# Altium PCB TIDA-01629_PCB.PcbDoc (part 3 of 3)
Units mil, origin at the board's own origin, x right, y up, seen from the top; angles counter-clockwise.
Board outline 2351.88 x 2559.06 mil, 4 copper layers (Top Layer, GND, POWER, Bottom Layer), stack 60.63 mil thick; 223 components, 122 nets, 655 pads, 542 vias.
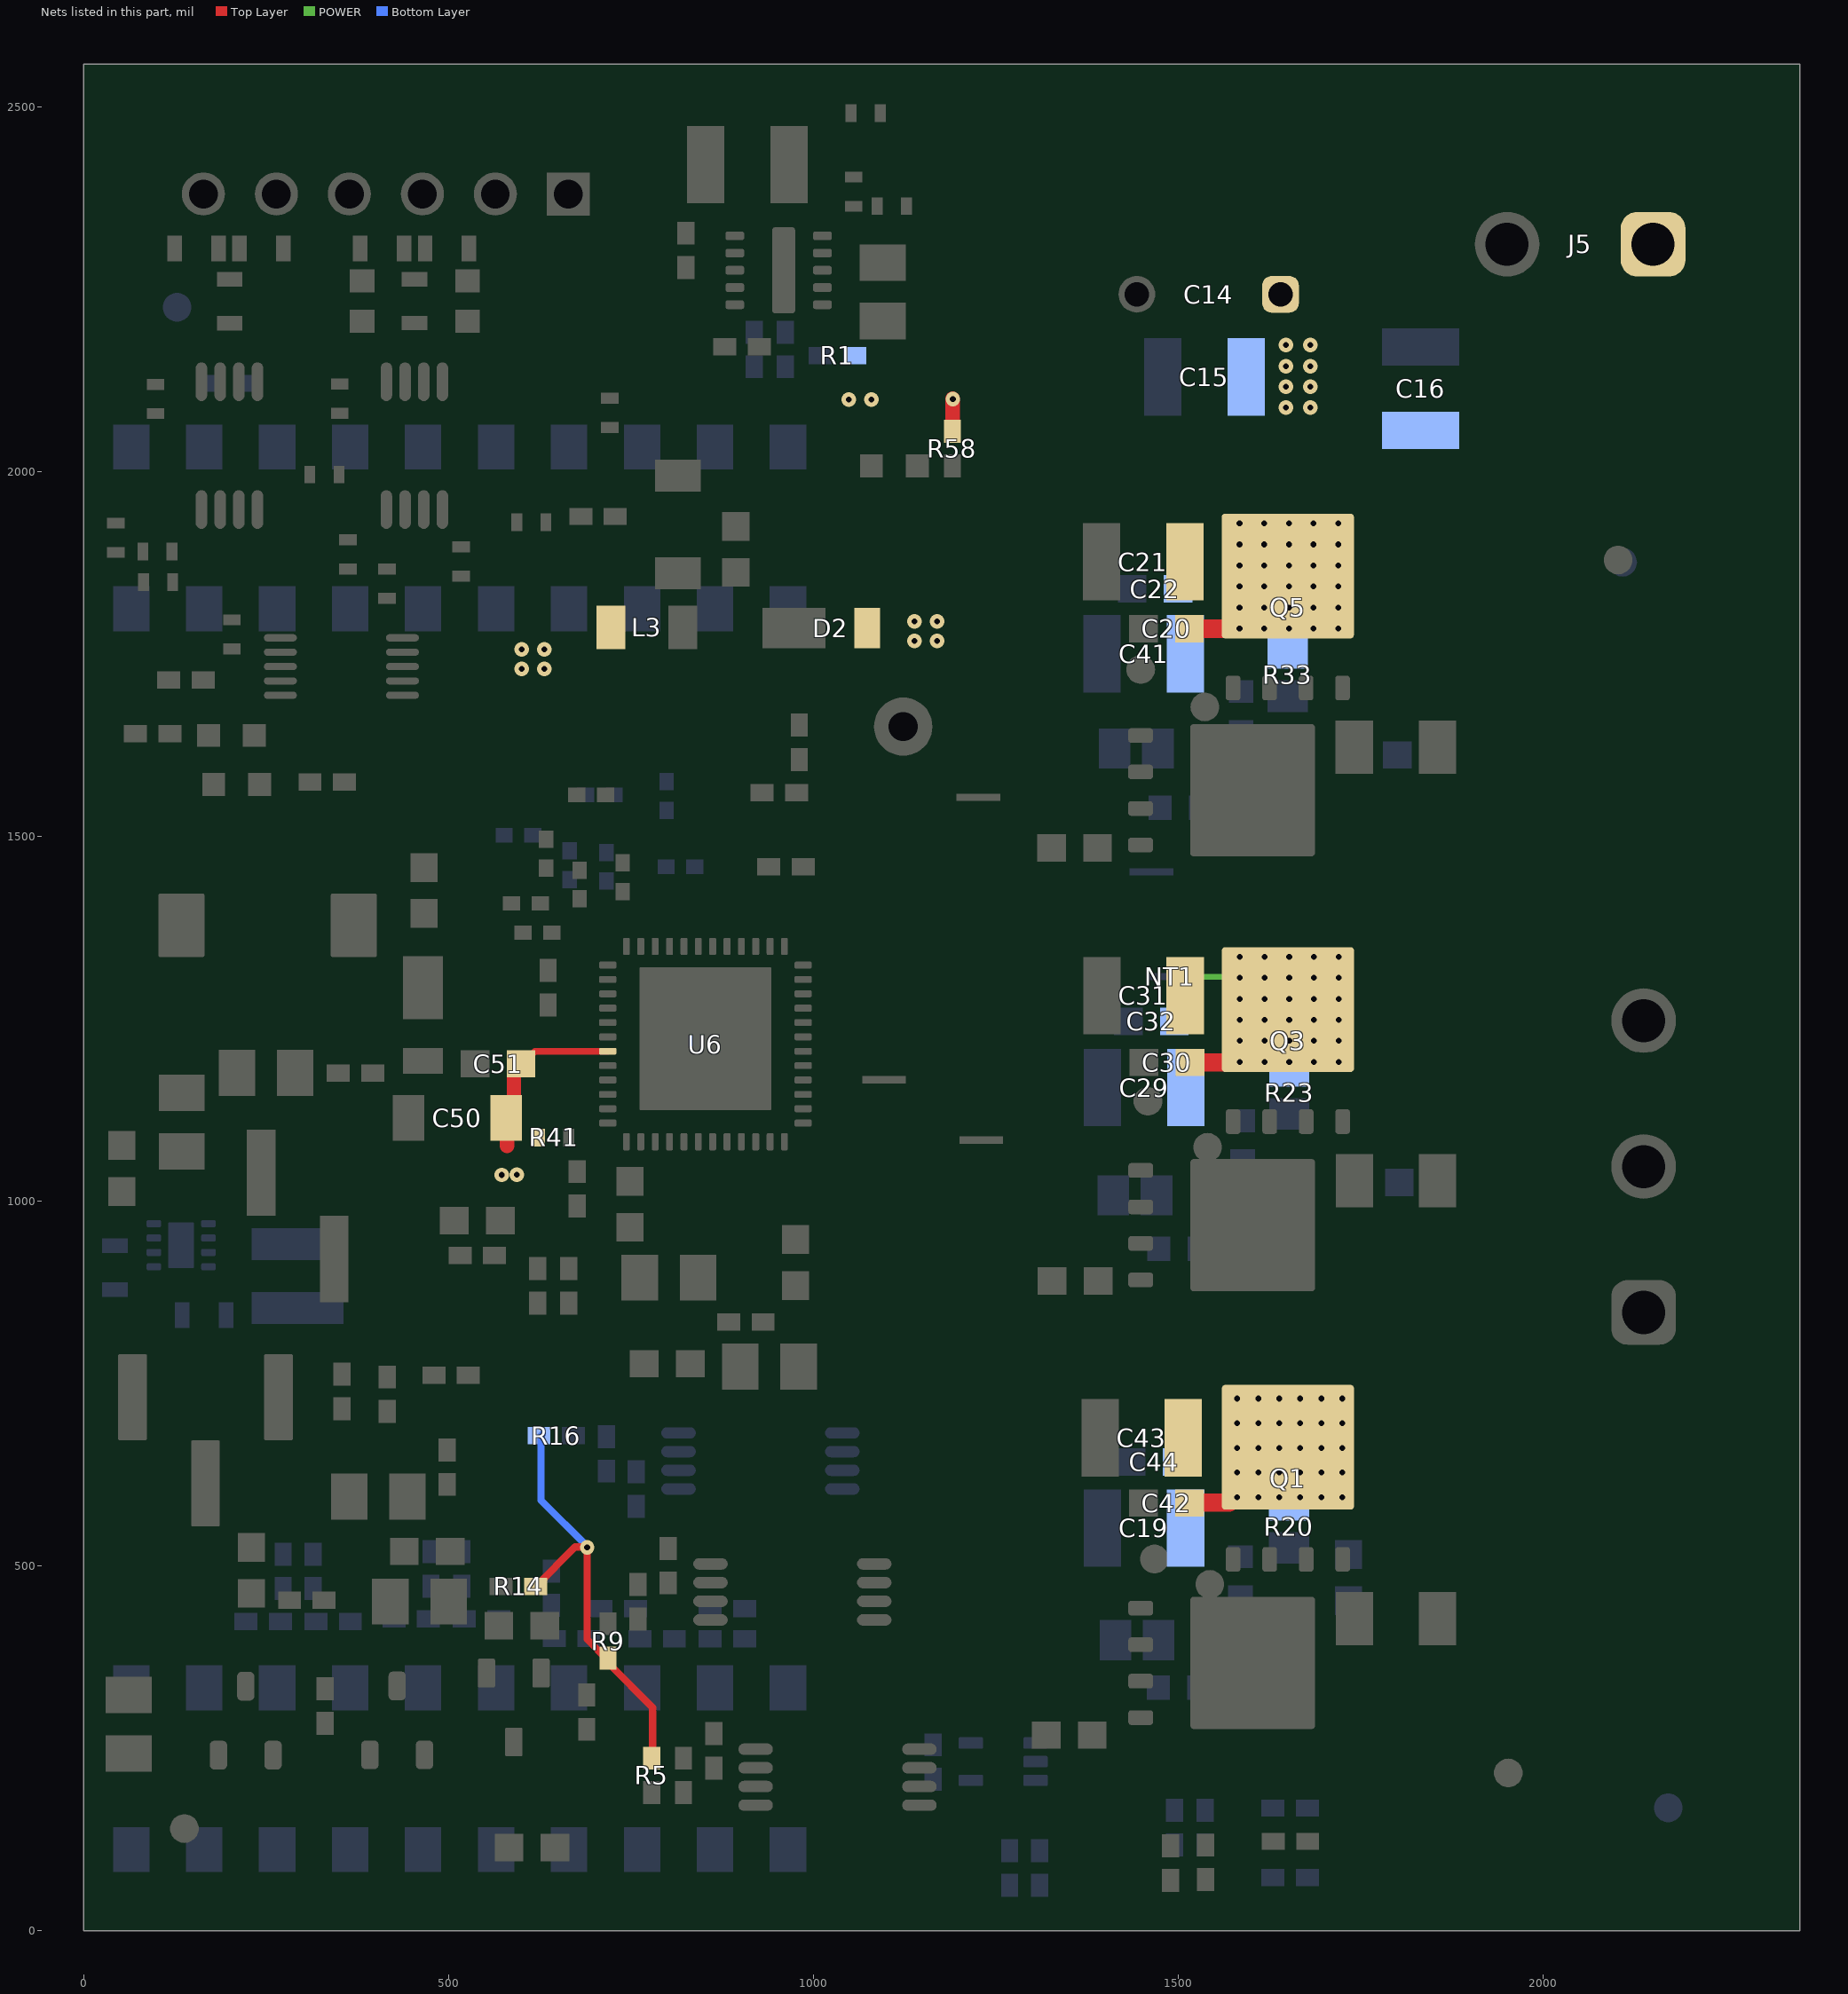
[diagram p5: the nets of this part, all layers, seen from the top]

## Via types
v1: diameter 20, hole 8, Top Layer to Bottom Layer, tented both sides, 525 vias
v2: diameter 19.68, hole 7.87, Top Layer to Bottom Layer, 17 vias

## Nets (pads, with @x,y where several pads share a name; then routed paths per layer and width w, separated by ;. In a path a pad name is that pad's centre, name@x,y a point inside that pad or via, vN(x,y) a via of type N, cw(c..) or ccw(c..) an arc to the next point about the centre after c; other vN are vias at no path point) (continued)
Vin: C14.1 C15.1 C16.1 C19.1 C20.1 C21.1 C22.1 C29.1 C30.1 C31.1 C32.1 C41.1 C42.1 C43.1 C44.1 D2.2 J5.1 NT1.2 Q1.5 Q1.6 Q1.7 Q1.8 Q1.9@1650.49,662.94 Q3.5 Q3.6 Q3.7 Q3.8 Q3.9@1650.49,1262.92 Q5.5 Q5.6 Q5.7 Q5.8 Q5.9@1650.36,1857.21 R1.1 R20.2 R23.2 R33.2 R58.2 | length 286.2
  Top Layer w20: R58.2@1191.05,2053.88 v1@1191.05,2100.27
  Top Layer w25: C20.1@1515.52,1784.92 Q5.9@1568.99,1784.92 ; C42.1@1515.68,586.51 1515.96,586.51 1516.52,587.07 Q1.9@1569.85,587.07 ; C30.1@1516.29,1190.55 Q3.9@1569.97,1190.55
  POWER w8: 1504.37,1307.87 v1@1582.68,1307.87
  other v1: 1581.04,594.57 1609.85,594.57 1638.66,594.57 1667.46,594.57 1696.27,594.57 1725.07,594.57 1581.04,628.37 1609.85,628.37 1638.66,628.37 1667.46,628.37 1696.27,628.37 1725.07,628.37 1581.04,662.17 1609.85,662.17 1638.66,662.17 1667.46,662.17 1696.27,662.17 1725.07,662.17 1581.04,695.97 1609.85,695.97 1638.66,695.97 1667.46,695.97 1696.27,695.97 1725.07,695.97 1581.04,729.76 1609.85,729.76 1638.66,729.76 1667.46,729.76 1696.27,729.76 1725.07,729.76 1584.73,1191.2 1618.53,1191.2 1652.33,1191.2 1686.12,1191.2 1719.92,1191.2 1584.73,1220.01 1618.53,1220.01 1652.33,1220.01 1686.12,1220.01 1719.92,1220.01 1584.73,1248.81 1618.53,1248.81 1652.33,1248.81 1686.12,1248.81 1719.92,1248.81 1584.73,1277.62 1618.53,1277.62 1652.33,1277.62 1686.12,1277.62 1719.92,1277.62 1584.73,1306.42 1618.53,1306.42 1652.33,1306.42 1686.12,1306.42 1719.92,1306.42 1584.73,1335.23 1618.53,1335.23 1652.33,1335.23 1686.12,1335.23 1719.92,1335.23 1138.63,1768.24 1169.56,1768.24 1584.24,1785.19 1618.04,1785.19 1651.84,1785.19 1685.64,1785.19 1719.43,1785.19 1138.63,1795.18 1169.56,1795.18 1584.24,1813.99 1618.04,1813.99 1651.84,1813.99 1685.64,1813.99 1719.43,1813.99 1584.24,1842.8 1618.04,1842.8 1651.84,1842.8 1685.64,1842.8 1719.43,1842.8 1584.24,1871.6 1618.04,1871.6 1651.84,1871.6 1685.64,1871.6 1719.43,1871.6 1584.24,1900.41 1618.04,1900.41 1651.84,1900.41 1685.64,1900.41 1719.43,1900.41 1584.24,1929.21 1618.04,1929.21 1651.84,1929.21 1685.64,1929.21 1719.43,1929.21 1647.67,2087.94 1681.17,2087.94 1048.85,2099.23 1079.77,2099.23 1191.32,2099.36 1647.67,2116.75 1681.17,2116.75 1647.67,2144.78 1681.17,2144.78 1647.67,2173.58 1681.17,2173.58
Vin_Connected: C50.1 C51.1 L3.2 R41.2 U6.43 | length 232.1
  Top Layer w9: C51.1@589.86,1177.04 618.6,1205.78 U6.43@718.5,1205.78
  Top Layer w20: 580.49,1076.06 C50.1@580.49,1120.72 ; C50.1@589.86,1130.2 C51.1@589.86,1177.04
  other v1: 573.09,1036.3 594.03,1036.54 600.78,1729.8 631.71,1729.8 600.78,1756.73 631.71,1756.73
Vref: R5.2 R9.2 R14.1 R16.2 | length 599.4
  Top Layer w10: R14.1@619.67,472.14 673.91,526.38 v1@690.17,526.38 ; v1@690.2,525.17 690.2,399.84 718.94,371.1 R9.2@718.94,369.07 ; R9.2@718.55,367.6 780.05,306.1 R5.2@780.05,236.6
  Bottom Layer w10: R16.2@628.74,680.7 626.91,678.87 626.91,590.19 690.71,526.39 v1@691.15,526.39
  other v1: 690.26,525.73
pads on no net: FID1.1 FID2.1 FID3.1 FID4.1 FID5.1 FID6.1 J2.2 J2.3 J2.5 J2.7 J2.11 J2.17 J2.19 J3.10 J3.17 J3.19 LBL1.0 Q1.9@1592.62,613.33 Q1.9@1592.62,679.48 Q1.9@1650.49,613.33 Q1.9@1650.49,679.48 Q1.9@1708.36,613.33 Q1.9@1708.36,679.48 Q2.9@1552.62,309.61 Q2.9@1552.62,367.48 Q2.9@1552.62,425.36 Q2.9@1618.76,309.61 Q2.9@1618.76,367.48 Q2.9@1618.76,425.36 Q3.9@1592.62,1213.31 Q3.9@1592.62,1279.45 Q3.9@1650.49,1213.31 Q3.9@1650.49,1279.45 Q3.9@1708.36,1213.31 Q3.9@1708.36,1279.45 Q4.9@1552.62,909.53 Q4.9@1552.62,967.41 Q4.9@1552.62,1025.28 Q4.9@1618.76,909.53 Q4.9@1618.76,967.41 Q4.9@1618.76,1025.28 Q5.9@1592.49,1807.6 Q5.9@1592.49,1873.75 Q5.9@1650.36,1807.6 Q5.9@1650.36,1873.75 Q5.9@1708.24,1807.6 Q5.9@1708.24,1873.75 Q6.9@1552.49,1505.7 Q6.9@1552.49,1563.58 Q6.9@1552.49,1621.45 Q6.9@1618.63,1505.7 Q6.9@1618.63,1563.58 Q6.9@1618.63,1621.45 U5.1 U5.5 U6.12 U6.13 U6.22 U6.23 U6.24 U6.25 U6.26 U6.49@794.09,1161.21 U6.49@794.09,1223.02 U6.49@794.09,1284.83 U6.49@852.36,1161.21 U6.49@852.36,1223.02 U6.49@852.36,1284.83 U6.49@910.63,1161.21 U6.49@910.63,1223.02 U6.49@910.63,1284.83 U7.8 U7.9@133.85,922.19 U7.9@133.85,957.62 U8.5 U8.8 U8.9 U8.10 U8.11@959.49,2235.64 U8.11@959.49,2276.19 U8.11@959.49,2316.74

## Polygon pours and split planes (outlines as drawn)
NetC71_1 on Top Layer "TOP_LAYER_NETC71_1_P292" (solid, pour order 292): 427.05,2326.37 433,2332.33 475.14,2332.33 480.26,2327.2 480.26,2255.74 472.86,2248.34 438.41,2248.34 427.05,2259.7
NetC73_1 on Top Layer "TOP_LAYER_NETC73_1_P300" (solid, pour order 300): 173.06,2329.76 178.47,2335.17 220.61,2335.17 225.73,2330.05 225.73,2258.59 218.33,2251.18 183.88,2251.18 173.06,2262
GND on Top Layer "TOP_LAYER_GND_P298" (solid, pour order 298): 433.68,2224.18 433.68,2186.57 454.57,2165.68 473.54,2184.64 473.54,2224.5 453.77,2244.27
Vencoder on Top Layer "TOP_LAYER_VENCODER_P296" (solid, pour order 296): 908.72,2320.71 904.92,2316.91 848.52,2316.91 842.1,2310.48 809.22,2310.48 790.37,2329.33 649.89,2329.33 625.72,2353.5 625.72,2407.62 649.77,2431.67 777.47,2431.67 823.37,2477.57 878.13,2477.57 882.63,2473.07 882.63,2336.42 885.78,2333.27 904.77,2333.27 908.71,2329.33
Vin on Top Layer "TOP_LAYER_VIN_P266" (solid, pour order 266): 1742.74,1952.25 1753.48,1941.51 1753.48,1763.82 1732.42,1742.76 1501.48,1742.76 1481.93,1762.31 1481.93,1930.38 1503.8,1952.25
Vin on Top Layer "TOP_LAYER_VIN_P264" (solid, pour order 264): 1738.52,1353.93 1749.26,1343.19 1749.26,1183.64 1709.28,1143.66 1516.16,1143.66 1477.72,1182.11 1477.72,1332.07 1499.58,1353.93
Vin on Top Layer "TOP_LAYER_VIN_P262" (solid, pour order 262): 1740.82,754.85 1751.56,744.11 1751.56,584.56 1709.05,542.05 1514.03,542.05 1480.02,576.07 1480.02,732.99 1501.88,754.85
3V3_Launch on Top Layer "TOP_LAYER_3V3_LAUNCH_P252" (solid, pour order 252): 95.75,171.95 86.43,162.63 39.81,162.63 28.04,174.4 28.04,267.26 34.06,273.29 89.38,273.29 95.75,266.92
3V3 on Top Layer "TOP_LAYER_3V3_P250" (solid, pour order 250): 30.48,403.6 39.81,412.92 86.42,412.92 98.2,401.15 98.2,300.3 92.31,294.42 33.67,294.42 30.48,297.61
NetC57_1 on Top Layer "TOP_LAYER_NETC57_1_P246" (solid, remove dead copper, pour order 246): 21.46,963.52 21.46,1027.15 30.97,1036.66 72.63,1036.66 78.9,1030.39 78.9,962.55 70.78,954.44 30.54,954.44
NetC11_1 on Top Layer "TOP_LAYER_NETC11_1_P238" (solid, remove dead copper, pour order 238): 489.09,545.42 549.35,545.42 589.95,504.83 589.95,345.69 574.5,330.24 539.65,330.24 520.61,349.28 520.61,387.36 493.31,414.66 478.58,414.66 468.88,424.36 468.88,525.21
NetR15_1 on Top Layer "TOP_LAYER_NETR15_1_P236" (solid, pour order 236): 606.65,442.22 652.49,442.22 661.97,432.73 661.97,350.93 665.92,346.98 698.72,346.98 707.02,338.68 707.02,309.05 702.67,304.7 639.45,304.7 600.33,343.82 600.33,436.68 605.86,442.21
Vin_Connected on Top Layer "TOP_LAYER_VIN_CONNECTED_P228" (solid, remove dead copper, pour order 228): 737.36,1718.29 587.64,1718.29 577.58,1728.35 577.58,1759.56 641.58,1823.55 743.21,1823.55 750.57,1816.19 750.57,1731.5
Vin_Connected on Top Layer "TOP_LAYER_VIN_CONNECTED_P226" (solid, pour order 226): 555.72,1090.04 555.72,1037.17 570.46,1022.43 602.33,1022.43 608.55,1028.66 608.55,1055.55 616.52,1063.51
GND on Top Layer "TOP_LAYER_GND_P224" (solid, remove dead copper, pour order 224): 666.57,1012.68 671.19,1017.3 692.52,1017.3 700.43,1025.21 700.43,1059.3 731.66,1090.52 731.66,1103.94 750.57,1103.94 754.31,1100.2 754.31,1072.27 721.76,1039.73 721.76,994.21 728.36,987.61 771.46,987.61 774.1,984.97 774.1,947.59 766.62,940.12 728.58,940.12 713.19,955.51 713.19,965.18 710.11,968.26 672.43,968.26 666.56,974.13
3V3_Analog on Top Layer "TOP_LAYER_3V3_ANALOG_P195" (solid, remove dead copper, pour order 195): 405.17,622.87 412.99,630.68 535.47,630.68 554.28,611.88 554.28,572.09 542.4,560.22 415.66,560.22 405.17,570.7
3V3 on Top Layer "TOP_LAYER_3V3_P194" (solid, remove dead copper, pour order 194): 532.72,713.13 534.58,713.13 540.96,706.75 540.96,668.46 515.53,643.02 468.35,643.02 464.11,647.26 464.11,698.38 478.93,713.19
NetC23_1 on Top Layer "TOP_LAYER_NETC23_1_P192" (solid, remove dead copper, pour order 192): 826.17,852.4 897.27,852.4 904.03,845.64 904.03,814.76 906.6,812.18 923.65,812.18 930.55,805.28 930.55,738.53 924.74,732.72 812.6,732.72 805.25,740.07 805.25,831.49
Vin_Connected on Top Layer "TOP_LAYER_VIN_CONNECTED_P188" (solid, pour order 188): 574.98,1210.27 620.32,1210.27 622.71,1207.88 622.71,1165.12 601.05,1143.46 601.05,1105.78 606.39,1100.44 636.45,1100.44 642.85,1094.04 642.85,1064.94 639.91,1062 560.78,1062 555.67,1067.12 555.67,1145.8 565.23,1155.37 574.98,1165.12
Vin on Top Layer "TOP_LAYER_VIN_P185" (solid, pour order 185): 1068.68,1832.31 1054.29,1817.93 1054.29,1751.44 1072.4,1733.34 1173.19,1733.34 1187.07,1747.22 1187.07,1814.21 1168.96,1832.31
NetC52_1 on Top Layer "TOP_LAYER_NETC52_1_P184" (solid, remove dead copper, pour order 184): 783.26,1768.32 805.03,1746.56 1010.59,1746.56 1033.35,1769.32 1033.35,1836.88 988.55,1881.68 810.47,1881.68 783.26,1854.48
GND on Top Layer "GND_PH_C" (solid, pour order 175): 1241.3,341.28 1254.53,328.04 1460.87,328.04 1472.16,339.33 1472.16,611.46 1453.87,629.76 1251.15,629.76 1241.38,619.99
GND on Top Layer "GND_PH_C" (solid, pour order 174): 1242.26,938.13 1255.5,924.89 1461.84,924.89 1473.13,936.18 1473.13,1208.32 1454.83,1226.62 1252.11,1226.62 1242.34,1216.85
GND on Top Layer "GND_PH_C" (solid, pour order 173): 1242.51,1536.71 1255.74,1523.48 1462.08,1523.48 1473.37,1534.77 1473.37,1806.9 1455.08,1825.2 1252.36,1825.2 1242.59,1815.43
PH_A_N on Top Layer "SW_C" (solid, pour order 172): 1558.41,525.62 1520.74,487.95 1520.74,464.26 1516.2,459.72 1516.2,273.64 1536.67,253.17 1711.04,253.17 1767.2,309.34 1767.2,464.98 1761.75,470.43 1700.91,470.43 1689.47,481.87 1689.47,522.94 1686.78,525.62
PH_B_N on Top Layer "SW_B" (solid, pour order 171): 1563.13,1127.09 1512.16,1076.12 1512.16,865.6 1535.06,842.7 1719.01,842.7 1767.08,890.77 1767.08,1065.33 1762.12,1070.29 1700.64,1070.29 1689.2,1081.74 1689.2,1122.8 1684.91,1127.09
PH_C_N on Top Layer "SW_C" (solid, pour order 170): 1546.58,1720.8 1515.94,1690.15 1515.93,1461.07 1537.55,1439.45 1718.52,1439.45 1766.94,1487.87 1766.94,1660.15 1761.49,1665.6 1700.64,1665.6 1689.2,1677.05 1689.2,1718.11 1686.52,1720.8
Vin on Top Layer "TOP_LAYER_VIN_P162" (solid, pour order 162): 1742.07,746.43 1737.55,750.94 1557.87,750.94 1553.35,746.43 1553.35,580.61 1559.16,574.81 1733.68,574.81 1742.07,583.19
GND on Top Layer "PowerSupply_GND" (solid, pour order 177): 345.97,1210.29 345.97,1190.71 345.97,1065.71 361.42,1050.26 440.43,1050.26 557.84,1167.67 557.84,1210.26 426.07,1210.28
NetC47_1 on Top Layer "Buck_SW" (solid, pour order 176): 332.91,1426.41 324.95,1418.45 324.95,1311.59 338.4,1298.14 407.16,1298.14 425.6,1279.7 425.6,1238.6 443.9,1220.3 718.86,1220.3 726.02,1227.46 726.02,1229.76 722.56,1233.22 610,1233.22 490.14,1353.08 490.14,1412.52 476.25,1426.41
NetC48_1 on Top Layer "15V_buck_out" (solid, pour order 179): 165.7,1435.57 171.73,1435.57 181.39,1425.92 181.39,1269 240.53,1209.85 240.53,1138.64 217,1115.1 106.08,1115.1 95.62,1125.56 95.62,1425.16 105.88,1435.41
GND on Top Layer "TOP_GND_PLANE" (solid, remove dead copper, pour order 306): 24.82,2504.52 61.52,2541.22 2282.94,2541.22 2324.99,2499.16 2324.99,91.46 2256.65,23.12 77.84,23.12 24.82,76.14
GND on GND "INNER_GND_BUCK" (solid, pour order 178): 346.18,1066.79 362.39,1050.58 414.92,1050.58 555.36,1191.02 799.4,1191.02 814.82,1206.45 814.82,1211.7 808.85,1217.68 372.84,1217.68 346.18,1191.02
GND on GND "TOP_GND_PLANE" (solid, remove dead copper, pour order 304): 26.5,2331.63 230.23,2535.36 2289.06,2535.36 2326.67,2497.75 2326.67,92.74 2258.33,24.4 79.52,24.4 26.5,77.42
PH_C_N on GND "SW_C" (solid, pour order 324): 1520.48,1637.67 1520.48,1456.82 1524.54,1452.76 1726.16,1452.76 1766.94,1493.54 1766.94,1637.71
PH_B_N on GND "SW_B" (solid, pour order 326): 1555.39,1070.91 1527.05,1070.91 1511.73,1055.59 1511.73,865.81 1535.06,842.48 1718.58,842.48 1771.12,895.02 1771.12,1063.7 1763.91,1070.91
PH_A_N on GND "SW_A" (solid, pour order 328): 1548.68,474.18 1520.34,474.18 1515.8,469.64 1515.8,273.26 1534.86,254.2 1712.72,254.2 1766.81,308.29 1766.81,461.97 1754.57,474.21 1520.34,474.18
3V3 on POWER "POWER_3V3_P244" (solid, remove dead copper, pour order 244): 297.54,810.02 297.54,816.85 307.34,826.65 377.7,826.65 486.07,718.28 520.5,718.28 538.91,699.88 538.91,698.99 517.97,678.04 421.46,678.04 297.54,801.96
PH_B_N on POWER "SW_B" (solid, pour order 223): 1555.39,1070.91 1527.05,1070.91 1511.73,1055.59 1511.73,865.81 1535.06,842.48 1718.58,842.48 1771.12,895.02 1771.12,1063.7 1763.91,1070.91
PH_A_N on POWER "SW_A" (solid, pour order 217): 1548.68,474.18 1520.34,474.18 1515.8,469.64 1515.8,273.26 1534.86,254.2 1712.72,254.2 1766.81,308.29 1766.81,461.97 1754.57,474.21 1520.34,474.18
PH_C_N on POWER "SW_C" (solid, pour order 214): 1520.48,1637.67 1520.48,1456.82 1524.54,1452.76 1726.16,1452.76 1766.94,1493.54 1766.94,1637.71
3V3_Analog on POWER "POWER_3V3_ANALOG_P196" (solid, remove dead copper, pour order 196): 546.55,630.95 529.59,613.99 529.59,573.27 548.31,554.55 833.24,554.55 845.96,541.83 845.96,296.87 867.07,275.76 899.77,275.76 908.14,284.14 908.14,604.01 881.76,630.39 861.04,630.39
Vin_Connected on POWER "POWER_VIN_CONNECTED_P183" (solid, pour order 183): 562.77,1757.46 573.98,1768.67 650.46,1768.67 654.48,1764.66 654.48,1352.57 607.89,1305.98 607.89,1030.67 602.86,1025.64 568.08,1025.64 562.77,1030.95
Vin on POWER "POWER_VIN" (solid, remove dead copper, pour order 164): 1371.46,2113.27 1025.76,2113.29 1025.76,1864.24 1216.54,1673.46 1216.54,618.2 1267.72,567.02 2287.31,567.02 2326.52,606.22 2326.17,2044.3 2326.52,2393.45 2300,2419.97 2090.03,2419.97 2060.06,2390 2060.06,2267.24 2030.52,2237.7 1884.77,2237.7 1808.92,2313.55 1577.87,2313.55 1549,2284.68 1549,2113.29
Vin on POWER "POWER_VIN_P206" (solid, remove dead copper, pour order 206): 1558.28,1949.26 1558.28,1789.58 1575.7,1772.17 1904.61,1772.17 1921.05,1788.61 1921.05,1932.27 1897.55,1955.77 1564.8,1955.77
Vin on POWER "POWER_VIN_P208" (solid, remove dead copper, pour order 208): 1556.63,1348 1556.63,1188.32 1574.05,1170.9 1902.95,1170.9 1919.4,1187.35 1919.4,1331 1895.89,1354.51 1563.14,1354.51
Vin on POWER "POWER_VIN_P207" (solid, remove dead copper, pour order 207): 1547.05,747.72 1547.05,588.04 1564.47,570.63 1893.37,570.63 1909.82,587.08 1909.82,730.73 1886.31,754.24 1553.56,754.24
GND on POWER "POWER_GND_P186" (solid, remove dead copper, pour order 186): 1959.06,2495.31 2042.57,2412.29 2042.57,2292.86 1871.92,2292.86 1829.71,2335.07 1562.79,2335.07 1531.51,2305.85 1531.51,2146.16 1148.76,2146.16 943.22,2146.16 943.22,2329.11 1067.27,2329.11 1233.48,2495.31
Vin on POWER "POWER_VIN_P288" (solid, pour order 288): 1577.87,2313.55 1706.77,2313.55 1735.64,2284.68 1735.64,2094.02 1565.12,2094.02 1546.32,2112.82 1546.32,2282
Vin on Bottom Layer "BOTTOM_LAYER_VIN_P286" (solid, remove dead copper, pour order 286): 1576.81,2294.58 1686.34,2294.58 1715.51,2265.41 1715.51,2149.89 1772.89,2092.51 1566.74,2092.51 1553.32,2105.93 1554.66,2107.27 1554.66,2272.42
Vin on Bottom Layer "BOTTOM_LAYER_VIN_P284" (solid, pour order 284): 2060,2533.98 2290.51,2533.98 2327.37,2497.12 2327.37,2099.8 2281.12,2053.54 1935.96,2053.54 2060,2177.59
Vin on Bottom Layer "BOTTOM_LAYER_VIN_P280" (solid, pour order 280): 1728.47,1939.34 1735.02,1932.79 1735.02,1762.25 1731.61,1758.83 1697.73,1758.83 1689.47,1750.57 1560.21,1750.57 1551.1,1741.46 1551.1,1695.91 1545.12,1689.93 1485.61,1689.93 1480.49,1695.05 1480.49,1859.82 1486.55,1865.88 1554.8,1865.88 1559.64,1870.72 1559.64,1919.98 1579,1939.34
Vin on Bottom Layer "BOTTOM_LAYER_VIN_P278" (solid, pour order 278): 1728.92,753.14 1735.47,746.59 1735.47,576.05 1732.05,572.63 1698.17,572.63 1689.91,564.37 1560.65,564.37 1551.54,555.26 1551.54,509.71 1545.56,503.73 1486.06,503.73 1480.93,508.85 1480.93,669.43 1491.18,679.68 1555.24,679.68 1560.08,684.52 1560.08,733.78 1579.44,753.14
Vin on Bottom Layer "BOTTOM_LAYER_VIN_P272" (solid, pour order 272): 1727.05,1349.3 1733.6,1342.75 1733.6,1172.2 1730.19,1168.79 1696.31,1168.79 1688.05,1160.53 1558.79,1160.53 1549.68,1151.42 1549.68,1105.87 1543.7,1099.89 1484.19,1099.89 1479.07,1105.01 1479.07,1265.59 1489.32,1275.84 1553.38,1275.84 1558.22,1280.68 1558.22,1329.94 1577.58,1349.3
GND on Bottom Layer "TOP_GND_PLANE" (solid, remove dead copper, pour order 308): 24.22,2505.35 53.01,2534.14 2290.89,2534.14 2324.39,2500.64 2324.39,91.72 2256.04,23.38 77.24,23.38 24.22,76.4
3V3_Launch on Bottom Layer "BOTTOM_LAYER_3V3_LAUNCH_P254" (solid, pour order 254): 97.93,86.45 88.6,77.13 41.99,77.13 30.21,88.9 30.21,181.76 36.23,187.79 91.56,187.79 97.93,181.42
3V3 on Bottom Layer "BOTTOM_LAYER_3V3_P248" (solid, remove dead copper, pour order 248): 97.88,555.16 97.88,391.6 85.47,379.19 44.98,379.19 30.14,394.03 30.14,539.93 51.11,560.9
NetC57_1 on Bottom Layer "BOTTOM_LAYER_NETC57_1_P242" (solid, remove dead copper, pour order 242): 21.26,978.23 70.55,978.23 77.91,970.87 77.91,964.4 81.7,960.6 104.68,960.6 110.92,954.36 110.92,927.15 106.91,923.13 25.27,923.13 14.79,933.62 14.79,972.6 20.44,978.25
3V3 on Bottom Layer "3V3" (solid, pour order 168): 181.76,789.62 181.76,865.08 193.44,876.76 356.95,876.76 382.36,851.36 382.36,810.66 353.37,781.67 189.7,781.67
PH_B_N on Bottom Layer "SW_B" (solid, pour order 222): 1556.24,1071.33 1527.9,1071.33 1512.58,1056.01 1512.58,866.24 1535.91,842.91 1719.43,842.91 1771.97,895.44 1771.97,1064.13 1764.76,1071.33
PH_A_N on Bottom Layer "SW_A" (solid, pour order 218): 1548.68,473.68 1520.34,473.68 1515.8,469.14 1515.8,272.94 1535.04,253.71 1712.72,253.71 1766.81,307.79 1766.81,461.47 1754.57,473.71 1520.34,473.68
PH_C_N on Bottom Layer "SW_C" (solid, pour order 215): 1548.81,1659.43 1520.48,1659.43 1515.94,1654.89 1515.93,1461.36 1537.84,1439.45 1712.85,1439.45 1766.94,1493.54 1766.94,1647.22 1754.7,1659.46 1520.48,1659.43
PH_C_N on Bottom Layer "BOTTOM_LAYER_PH_C_N_P205" (solid, remove dead copper, pour order 205): 1534.52,1657.31 1608.86,1657.31 1611.76,1654.41 1611.76,1542.7 1575.22,1506.15 1518.74,1506.15 1514.59,1510.3 1514.59,1637.38
PH_B_N on Bottom Layer "BOTTOM_LAYER_PH_B_N_P204" (solid, remove dead copper, pour order 204): 1532.86,1064.7 1607.19,1064.7 1610.1,1061.79 1610.1,950.08 1573.56,913.54 1517.08,913.54 1512.92,917.69 1512.92,1044.77
PH_A_N on Bottom Layer "BOTTOM_LAYER_PH_A_N_P203" (solid, remove dead copper, pour order 203): 1531.61,462.12 1605.95,462.12 1608.86,459.21 1608.86,347.5 1572.31,310.96 1515.83,310.96 1511.68,315.11 1511.68,442.19
GND on Bottom Layer "BOTTOM_LAYER_GND_P202" (solid, remove dead copper, pour order 202): 1371.26,612.28 1363.22,604.24 1363.22,375.1 1375.28,363.04 1421.51,363.04 1430.05,371.58 1430.05,602.73 1420.55,612.24 1408.12,612.24
GND on Bottom Layer "BOTTOM_LAYER_GND_P201" (solid, remove dead copper, pour order 201): 1368.63,1215.91 1360.59,1207.87 1360.59,978.73 1372.65,966.67 1418.88,966.67 1427.43,975.21 1427.43,1206.36 1417.92,1215.87 1405.49,1215.87
GND on Bottom Layer "BOTTOM_LAYER_GND_P200" (solid, remove dead copper, pour order 200): 1365.59,1811.16 1357.55,1803.12 1357.55,1573.98 1369.61,1561.92 1415.84,1561.92 1424.39,1570.47 1424.39,1801.62 1414.88,1811.12 1402.45,1811.12
Vin on Bottom Layer "BOTTOM_LAYER_VIN_P199" (solid, remove dead copper, pour order 199): 1521.95,1803.36 1622.86,1803.36 1635.56,1790.66 1635.56,1785.17 1624.23,1773.84 1533.28,1773.84 1518.52,1788.6
Vin on Bottom Layer "BOTTOM_LAYER_VIN_P198" (solid, remove dead copper, pour order 198): 1522.5,605.53 1623.41,605.53 1636.1,592.83 1636.1,587.34 1624.78,576.02 1533.83,576.02 1519.07,590.77
Vin on Bottom Layer "BOTTOM_LAYER_VIN_P182" (solid, pour order 182): 1095.04,2170.04 1088.85,2176.23 1039.8,2176.23 1035.32,2171.74 1035.32,2089.96 1042.51,2082.77 1093.06,2082.77 1095.1,2084.81
Vin on Bottom Layer "BOTTOM_LAYER_VIN_P209" (solid, remove dead copper, pour order 209): 1596.66,604.7 1632.4,640.44 1686.46,640.44 1711.99,614.91 1711.99,581.87 1705.95,575.83 1671.64,575.83
Vin on Bottom Layer "BOTTOM_LAYER_VIN_P211" (solid, remove dead copper, pour order 211): 1589.36,1801.84 1618.06,1830.55 1684.37,1830.55 1701.73,1813.19 1701.73,1780.16 1695.69,1774.12 1661.38,1774.12
Vin on Bottom Layer "POWER_VIN" (solid, remove dead copper, pour order 302): 1553.25,2106.66 1475.92,2029.33 1475.92,625.76 1539.22,562.45 2297.96,562.46 2327.08,591.57 2327.08,2106.66
no net on Bottom Solder "BOTTOM_LAYER_NONET_P160" (solid, pour order 8): 1805.34,469.82 1801.48,465.95 1801.48,375.86 1808.56,368.78 1863.58,368.78 1875.8,381.01 1875.8,456.95 1862.93,469.82
PH_A_N on Bottom Solder "BOTTOM_LAYER_NONET_P160" (solid): 1693.81,468.3 1689.95,464.44 1689.95,374.35 1697.03,367.27 1752.05,367.27 1764.28,379.49 1764.28,455.43 1751.41,468.3

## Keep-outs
Keep-Out Layer:
  text ".Layer_Name" at 536.41,-906.9 h60

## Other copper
Top Layer:
  pour cut-out: 376.42,218.92 376.4,154.62 349.03,182 349.03,211.97 355.98,218.92
  pour cut-out: 557.84,1206.94 557.84,1167.67 545.63,1155.46 545.63,1145.8 555.67,1145.8 574.98,1165.12 574.98,1207.22
  pour cut-out: 371.61,1561.39 425.8,1561.39 432.89,1554.3 432.89,1533.04 321.17,1421.33 321.17,1305.86 338.68,1288.36 406.21,1288.36 418.71,1275.85 418.71,1230.83 419.13,1230.42 418.3,1229.58 226.55,1229.58 211.13,1245.01
  region net Vencoder: 901.37,2317.3 866.68,2317.3 856.33,2327.65 856.33,2331.02 877.55,2352.24 899.55,2330.24 905.51,2330.24 908.87,2326.88 908.87,2320.92 905.22,2317.27 904.05,2317.27
  pour cut-out: 917.44,2333.19 909.21,2341.42 875.91,2341.42 867.68,2333.19 867.68,2219.19 878.21,2208.66 906.91,2208.66 917.44,2219.19
  pour cut-out: 987.76,2333.19 995.99,2341.42 1029.29,2341.42 1037.12,2333.58 1037.12,2243.93 1028.84,2235.65 996.44,2235.65 987.76,2244.32
  pour cut-out: 1152.83,439.51 1152.83,358.99 1193.09,318.73 1193.09,247.04 1207.82,232.31 1233.35,232.31 1233.35,388.45 1170.5,451.29
  pour cut-out: 1621.48,188.55 1621.48,26.44 1625.52,22.4 1656.1,22.4 1656.1,186.24 1657.83,187.97
  pour cut-out: 1745.99,1960.6 2317.14,1960.6 2328.66,1949.08 2327.02,1947.43 2327.02,1896.4 1759.16,1896.4 1754.22,1901.34
  region net PH_C_P: 1848.13,1696.82 1854.35,1696.82 1868.79,1696.82 1993.97,1696.82 2236.65,1454.14 2236.65,1234.65 2203.6,1201.6 2118.31,1201.6 1830.06,1489.85 1830.06,1678.75
  region net PH_B_P: 2197.92,1049.92 2197.92,1041.56 2197.92,954.18 2174.66,930.92 1844.45,930.92 1828.97,946.4 1828.97,1150.31 1846.76,1168.09 1846.76,1169.6 2178.64,1169.6 2197.92,1150.31 2197.92,1066.59 2197.92,1058.59
  region net PH_A_P: 1855.67,382.49 1996.17,382.49 2185.18,571.5 2185.18,881.7 2172.96,893.91 2081,893.91 1830.15,643.06 1830.15,390.09 1837.75,382.49 1847.66,382.49
  text ".Layer_Name" at 536.41,-906.9 h60
GND:
  pour cut-out: 163.45,938.24 159.15,933.95 159.15,922.14 162.37,918.92 356.5,918.92 361.69,924.11 361.69,959.18 354.54,966.33 228.93,966.33 218.56,955.96 218.56,948.08 208.71,938.24
  pour cut-out: 728.04,1235.69 731.01,1232.72 731.01,1220.49 726.71,1216.2 439.96,1216.2 419.15,1237.01 419.15,1275.66 402.63,1292.18 339.2,1292.18 319.38,1312 319.38,1419.7 331.27,1431.6 482.91,1431.6 496.78,1417.72 496.78,1354.62 613.64,1237.77 725.96,1237.77
Bottom Layer:
  pour cut-out: 363.34,915.36 366.04,912.65 366.04,881.87 361.59,877.43 357.15,881.87 351.09,881.87
  region: 1817.12,473.02 1803.57,473.02 1790.87,460.32 1790.87,269.45 1807.22,253.11 2300.41,253.11 2324.29,276.99 2324.29,448.57 2299.82,473.04
  pour cut-out: 1656.27,36.65 1656.27,25.06 1653.81,22.6 1623.64,22.6 1620.1,26.15 1620.1,55.6 1621.16,56.67 1653.81,56.67 1655.94,54.54
  pour cut-out: 1616.9,248.65 1637.48,248.65 1646,240.13 1646,188.32 1645.65,187.96 1608.74,187.96 1599.16,197.55 1599.16,247.23 1599.87,247.94
  pour cut-out: 1615.74,147.15 1615.74,100.91 1624.57,92.08 1638.08,92.08 1647.43,101.43 1641.2,107.67 1641.2,151.31
  text ".Layer_Name" at 536.41,-906.9 h60

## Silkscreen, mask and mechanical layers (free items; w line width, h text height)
Top Overlay:
  text "J3" at 63.02,1968.39 h28.5 r90
  text "Vin" at 2207.58,1916.77 h108.27 r90
  text "Vin" at 1087.9,1898.52 h108.27
  text "GND" at 1994.79,1873.64 h108.27 r90
  text "3V3" at 402.69,1613.84 h75
  text "15V" at 402.69,1557.89 h75
  text "C" at 1865.44,1309.16 h108.27 r90
  text "B" at 1866.65,1207.41 h108.27 r90
  text "A" at 1866.65,1104.59 h108.27 r90
  text "TIDA-01629 rev E1" at 1255.14,971 h108.27 r90
  text "J2" at 75.28,84.64 h28.5 r90
  text ".Layer_Name" at 536.41,-906.9 h60
Bottom Overlay:
  text ".Layer_Name" at 536.41,-906.9 h60
Top Paste:
  text ".Layer_Name" at 536.41,-906.9 h60
Bottom Paste:
  text ".Layer_Name" at 536.41,-906.9 h60
Top Solder:
  text ".Layer_Name" at 536.41,-906.9 h60
  text ".Layer_Name" at 536.41,-906.9 h60
Bottom Solder:
  text ".Layer_Name" at 536.41,-906.9 h60
Drill Guide:
  text ".Layer_Name" at 536.41,-906.9 h60
M1 Board Outline:
  the board outline again, w10
  text ".Layer_Name" at 536.41,-906.9 h60
M2 Board Dimensions:
  rectangle: 0,-243.11 125,-118.11
  rectangle: 125,-368.11 500,-243.11
  lines w7: 0,-243.11 1000,-243.11 ; 125,-368.11 125,-118.11 ; 250,-368.11 250,-118.11 ; 500,-368.11 500,-118.11 ; 750,-368.11 750,-118.11 ; 0,-368.11 1000,-368.11 1000,-118.11 0,-118.11 0,-368.11
  text ".Layer_Name" at 536.41,-906.9 h60
M3 3D STEP Top:
  text ".Layer_Name" at 536.41,-906.9 h60
M4 3D STEP Bottom:
  text ".Layer_Name" at 536.41,-906.9 h60
M5 Assembly Top:
  lines w10: -332.59,-978.57 6267.41,-978.57 ; -332.59,-775.24 6269.41,-775.24 ; -332.59,-571.91 -332.59,-1181.91 3672.41,-1181.91 6269.41,-1181.91 6269.41,-571.91 -332.09,-571.91 -332.09,-1181.91 1243.41,-1181.91 ; 2132.41,-1181.91 2132.41,-571.91 ; 3399.41,-775.24 3399.41,-571.91 ; 4239.41,-775.24 4239.41,-571.91 ; 4861.41,-1188.41 4861.41,-985.57
  text "COMPONENTS MARKED 'DNP' SHOULD NOT BE POPULATED." at 1112.91,-366.91 h60
  text "ASSEMBLY VARIANT:" at 1112.41,-482.41 h60
  text ".VariantName" at 2148.41,-482.41 h60
  text "PCB VIEWED FROM TOP SIDE" at -269.09,-704.07 h60
  text "BOARD #:" at 2207.41,-704.07 h60
  text ".PRJ_Number" at 2752.91,-704.07 h60
  text "REV:" at 3597.41,-704.07 h60
  text ".PCB_Rev" at 3888.91,-704.07 h60
  text "SVN REV:" at 4435.41,-704.07 h60
  text ".VersionControl_RevNumber" at 4941.41,-704.07 h60
  text "TID #:" at 2207.41,-907.41 h60
  text ".TID" at 2752.91,-907.41 h60
  text "PLOT NAME =" at -269.09,-1112.74 h60
  text ".plot_File_Name" at 536.41,-1112.74 h60
  text "GENERATED    :" at 2209.41,-1112.74 h60
  text ".Print_Date" at 3078.91,-1112.74 h60
  text ".Print_Time" at 3807.91,-1112.74 h60
  text "TEXAS INSTRUMENTS" at 5072.41,-1112.74 h60
M6 Assembly Bottom:
  lines w10: -333.09,-775.74 6268.91,-775.74 ; -331.09,-979.07 6268.91,-979.07 ; 1074.91,-1188.91 1074.91,-986.07 ; 1696.91,-775.74 1696.91,-572.41 ; 2536.91,-775.74 2536.91,-572.41 ; 3803.91,-1182.41 3803.91,-572.41 ; 4692.91,-1182.41 6268.41,-1182.41 6268.41,-572.41 -333.09,-572.41 -333.09,-1182.41 2263.91,-1182.41 6268.91,-1182.41 6268.91,-572.41
  text "COMPONENTS MARKED 'DNP' SHOULD NOT BE POPULATED." at 6061.41,-366.41 h60
  text ".VariantName" at 5017.41,-482.41 h60
  text "ASSEMBLY VARIANT:" at 6056.41,-482.41 h60
  text ".VersionControl_RevNumber" at 994.91,-704.57 h60
  text "SVN REV:" at 1500.91,-704.57 h60
  text ".PCB_Rev" at 2047.41,-704.57 h60
  text "REV:" at 2338.91,-704.57 h60
  text ".PRJ_Number" at 3183.41,-704.57 h60
  text "BOARD #:" at 3728.91,-704.57 h60
  text "PCB VIEWED FROM BOTTOM SIDE" at 6205.41,-704.57 h60
  text ".TID" at 3183.41,-907.91 h60
  text "TID #:" at 3728.91,-907.91 h60
  text "TEXAS INSTRUMENTS" at 863.91,-1113.24 h60
  text ".Print_Time" at 2128.41,-1113.24 h60
  text ".Print_Date" at 2857.41,-1113.24 h60
  text "GENERATED    :" at 3726.91,-1113.24 h60
  text ".plot_File_Name" at 5399.91,-1113.24 h60
  text "PLOT NAME =" at 6205.41,-1113.24 h60
M9 Title Sheet:
  drawing of 57 lines, arcs and shapes, not listed
  text "1" at 699.24,7988.09 h70
  text "2" at 3194.91,7988.09 h70
  text "3" at 5684.25,7988.09 h70
  text "4" at 8190.92,7988.09 h70
  text "5" at 10689.91,7988.09 h70
  text "6" at 13194.91,7988.09 h70
  text "A" at -457.09,6845.09 h70
  text "A" at 14342.91,6845.09 h70
  text "B" at -457.09,4465.09 h70
  text "B" at 14342.91,4465.09 h70
  text "C" at -457.09,2090.09 h70
  text "C" at 14342.91,2090.09 h70
  text "PROJECT TITLE:" at 11302.91,229.09 h45
  text ".PRJ_Title" at 11352.91,95.77 h70
  text "DESIGNED FOR:" at 11302.91,-71.91 h45
  text ".PRJ_Customer" at 11352.91,-211.91 h70
  text "D" at -457.09,-279.91 h70
  text "D" at 14342.91,-279.91 h70
  text "FILE NAME:" at 11302.91,-371.91 h45
  text ".PCB_File_Name_No_Path" at 11352.91,-491.91 h70
  text "Texas Instruments (TI) and/or its licensors do not warrant the accuracy or completeness of this specification" at 6333.41,-653.75 h45
  text "ENGINEER:" at 11302.91,-661.91 h45
  text "LAYOUT BY:" at 12807.91,-661.91 h45
  text "or any information contained therein. TI and/or its licensors do not warrant that this design will meet" at 6288.42,-766.41 h45
  text ".PRJ_Engineer" at 11352.91,-816.9 h70
  text ".PCB_Layout" at 12858.41,-816.9 h70
  text "the specifications, will be suitable for your application or fit for any particular purpose, or will operate in" at 6288.42,-879.08 h45
  text ".Layer_Name" at 536.41,-906.9 h60
  text "ALTIUM DESIGNER VERSION:" at 12807.91,-971.91 h45
  text "an implementation. TI and/or its licensors do not warrant that the design is production worthy. You should" at 6288.42,-991.74 h45
  text "completely validate and test your design implementation to confirm the system functionality for your application." at 6333.41,-1104.41 h45
  text ".print_Scale" at 11352.91,-1105.23 h70
  text ".Application_BuildNumber" at 12858.41,-1105.23 h70
  text "1" at 699.24,-1311.91 h70
  text "2" at 3194.91,-1311.91 h70
  text "3" at 5684.25,-1311.91 h70
  text "4" at 8190.92,-1311.91 h70
  text "5" at 10689.91,-1311.91 h70
  text "6" at 13194.91,-1311.91 h70
M10 Fab Notes:
  drawing of 189 lines, arcs and shapes, not listed
  text "DESIGN INFORMATION" at 12341.42,6307.77 h60
  text "MIN. TRACK WIDTH:" at 11696.87,6175.64 h60
  text "8" at 12793.11,6175.64 h60
  text "MIL" at 12947.87,6175.64 h60
  text "MIN. CLEARANCE:" at 11696.87,6051.51 h60
  text "0.2" at 12733.11,6051.52 h60
  text "mm" at 12947.87,6051.51 h60
  text "MIN. VIA PAD SIZE:" at 11696.87,5927.39 h60
  text "24" at 12763.12,5927.39 h60
  text "MIL" at 12947.87,5927.39 h60
  text "0.05mm (2MIL)" at 12391.87,5797.49 h60
  text "MINIMUM ANNULAR RING" at 11367.63,5789.27 h60
  text "EXTERNAL" at 13099.87,5789.27 h60
  text "PER" at 11567.63,5679.14 h60
  text "IPC-D-275 CLASS 2 LEVEL C" at 11787.63,5679.14 h60
  text "MIL, HOLES" at 13275.87,5578.66 h60
  text "+/-" at 12883.41,5570.08 h60
  text "+/-" at 13737.41,5570.08 h60
  text "REGISTRATION TOLERANCES:" at 11367.63,5569.01 h60
  text "METAL" at 12567.41,5569.01 h60
  text "5" at 13143.61,5569.01 h60
  text "3" at 13976.61,5569.01 h60
  text "MIL" at 14092.87,5569.01 h60
  text "HOLE SIZE TOLERANCE (UNLESS OTHERWISE SPECIFIED):" at 11367.63,5470.7 h60
  text "+/-" at 13737.41,5467.82 h60
  text "3" at 13976.61,5466.76 h60
  text "MIL" at 14092.87,5466.76 h60
  text "MATERIAL:" at 11292.87,5329.11 h60
  text "FR-4 High Tg" at 12279.31,5200.59 h60
  text "X" at 12134.87,5192.6 h60
  text "FR-408" at 11713.87,5188.08 h60
  text "OTHER" at 13201.87,5188.08 h60
  text "62 MIL (1.6mm) +/-10%" at 12033.97,5045.05 h60
  text "X" at 11913.87,5042.6 h60
  text "THICKNESS:" at 11367.63,5036.83 h60
  text "OTHER" at 13318.87,5036.83 h60
  text "TOLERANCE:" at 11367.63,4898.52 h60
  text "X" at 12215.87,4898.52 h60
  text "ANSI IPC-6012 TYPE 3 CLASS 2" at 12393.88,4898.52 h60
  text "OTHER +/-" at 12393.87,4754.33 h60
  text "BOW & TWIST:" at 11367.63,4609.14 h60
  text "X" at 12215.87,4609.14 h60
  text "ANSI IPC-6012 TYPE 3 CLASS 2" at 12393.88,4609.14 h60
  text "OTHER +/-" at 12393.87,4462.44 h60
  text "DRILLING:" at 11292.87,4331.82 h60
  text "NC_DRILL FILES" at 13053.87,4226.63 h60
  text "REFERENCE:" at 11367.63,4222.7 h60
  text "X" at 12024.87,4222.6 h60
  text "AS SHOWN" at 12202.87,4222.7 h60
  text "X" at 12925.87,4222.7 h60
  text "OTHER" at 13351.87,4080.44 h60
  text "PTH COPPER THICKNESS:" at 11367.31,4076.92 h60
  text "X" at 12506.55,4076.92 h60
  text "20-30 um" at 12634.54,4076.92 h60
  text "BOARD FINISH:" at 11292.87,3929.32 h60
  text "SILKSCREEN:" at 11448.09,3819.19 h60
  text "X" at 12405.87,3819.19 h60
  text "TOP" at 12522.87,3819.19 h60
  text "X" at 12915.87,3819.19 h60
  text "BOTTOM" at 13033.87,3819.19 h60
  text "SILKSCREEN COLOR:" at 11448.09,3664 h60
  text "X" at 12404.87,3664 h60
  text "WHITE" at 12522.87,3664 h60
  text "OTHER" at 13033.87,3664 h60
  text "X" at 12535.87,3520.56 h60
  text "GREEN" at 12653.87,3520.56 h60
  text "OTHER" at 13271.87,3520.56 h60
  text "SOLDER RESIST COLOR:" at 11448.09,3513.69 h60
  text "X" at 12535.87,3366.3 h60
  text "MATTE" at 12653.87,3366.3 h60
  text "SEMI-GLOSS" at 13271.41,3365.67 h60
  text "IMMERSION GOLD (ENIG)" at 12353.87,3193.53 h60
  text "ENEPIG" at 13691.41,3186.31 h60
  text "SURFACE FINISH:" at 11292.87,3185.31 h60
  text "X" at 12175.87,3185.31 h60
  text "IMM. TIN/SILVER OR EQUIV" at 11622.41,3048 h60
  text "OTHER" at 13053.87,3044.06 h60
  text "ARRAY/PANEL:" at 11292.87,2888.68 h60
  text "CUT AND TRIM PER M1 BOARD OUTLINE" at 12353.87,2880.46 h60
  text "N.C. ROUTE" at 12353.87,2744.49 h60
  text "X" at 13041.87,2744.49 h60
  text "V. SCORE" at 13219.87,2744.49 h60
  text "CERTIFICATION:" at 11292.87,2615.37 h60
  text "MATERIALS AND WORKMANSHIP FOR ALL PCBS" at 12017.87,2615.37 h60
  text "TO MEET OR EXCEED THE REQUIREMENTS OF:" at 12017.87,2521.3 h60
  text "X" at 11655.38,2392.67 h60
  text "ANSI IPC-A-600F CLASS ->" at 11783.37,2392.67 h60
  text "X" at 13431.38,2392.67 h60
  text "2" at 13541.37,2392.67 h60
  text "1" at 13226.37,2391.18 h60
  text "3" at 13895.37,2391.18 h60
  text "X" at 12467.38,2244.99 h60
  text "RoHS" at 12595.37,2244.99 h60
  text "OTHER" at 13239.77,2244.99 h60
  text "PER ORDER" at 13636.83,2244.99 h60
  text "ALL BOARDS MUST MEET OR EXCEED UL94-V0 REQUIREMENTS." at 11320.41,2091.16 h60
  text "PCB MUST BEAR THE UL94V-0 UL REGISTERED MATERIAL ID NUMBER" at 11320.41,1975.1 h60
  text "ADDITIONAL REQUIREMENTS:" at 11292.87,1805.67 h60
  text "MICROSECTION:" at 11367.63,1698.55 h60
  text "YES" at 12273.37,1698.55 h60
  text "REQUIRED" at 13134.87,1554.21 h60
  text "BARE BOARD ELEC. TEST:" at 11367.63,1551.36 h60
  text "NONE" at 12673.37,1551.36 h60
  text "X" at 13016.87,1551.36 h60
  text "PER ORDER" at 13726.87,1551.36 h60
  text "XX MIL VIAS REQUIRE NON-CONDUCTIVE FILL AND PLANARIZE" at 11535.78,1346.41 h59
  text "XX MIL VIAS REQUIRE CONDUCTIVE FILL AND PLANARIZE" at 11543.78,1242.44 h60
  text "OUTER XX MIL VIAS REQUIRE 50 OHM SINGLE-ENDED IMPEDANCE" at 11542.8,1079.05 h58
  text "LAYER 2 & 3 (INNER LAYERS) XX MIL WIDE, XX MIL SPACE / TRACES REQUIRE 100 OHM DIFFERENTIAL IMPEDANCE" at 11534.8,843.34 h60
  text ".Layer_Name" at 536.41,-906.9 h60
M11 Gerber Information:
  lines w10: -332.59,-978.57 6267.41,-978.57 ; -332.59,-775.24 6269.41,-775.24 ; -332.59,-571.91 -332.59,-1181.91 3672.41,-1181.91 6269.41,-1181.91 6269.41,-571.91 -332.09,-571.91 -332.09,-1181.91 1243.41,-1181.91 ; 2132.41,-1181.91 2132.41,-571.91 ; 3399.41,-775.24 3399.41,-571.91 ; 4239.41,-775.24 4239.41,-571.91 ; 4861.41,-1188.41 4861.41,-985.57
  text "ALL ARTWORK VIEWED FROM TOP SIDE" at -269.09,-704.07 h60
  text "BOARD #:" at 2207.41,-704.07 h60
  text ".PRJ_Number" at 2752.91,-704.07 h60
  text "REV:" at 3597.41,-704.07 h60
  text ".PCB_Rev" at 3888.91,-704.07 h60
  text "SVN REV:" at 4435.41,-704.07 h60
  text ".VersionControl_RevNumber" at 4941.41,-704.07 h60
  text "LAYER NAME =" at -269.09,-906.9 h60
  text "TID #:" at 2207.41,-907.41 h60
  text ".TID" at 2752.91,-907.41 h60
  text "PLOT NAME =" at -269.09,-1112.74 h60
  text ".plot_File_Name" at 536.41,-1112.74 h60
  text "GENERATED    :" at 2209.41,-1112.74 h60
  text ".Print_Date" at 3078.91,-1112.74 h60
  text ".Print_Time" at 3807.91,-1112.74 h60
  text "TEXAS INSTRUMENTS" at 5072.41,-1112.74 h60
M12 Stackup:
  drawing of 295 lines, arcs and shapes, not listed
  text "Layer" at 9779.25,7764.11 h60
  text "Name" at 10189.17,7764.11 h60
  text "Material" at 11118.91,7764.11 h60
  text "Thickness" at 11978.68,7764.11 h60
  text "Constant" at 12628.51,7764.11 h60
  text "Board Layer Stack" at 13198.37,7764.11 h60
  text "1" at 9779.25,7644.11 h60
  text "Top Overlay" at 10189.17,7644.11 h60
  text "2" at 9779.25,7524.11 h60
  text "Top Solder" at 10189.17,7524.11 h60
  text "Solder Resist" at 11118.91,7524.11 h60
  text "0,025mm" at 11978.68,7524.11 h60
  text "3,5" at 12628.51,7524.11 h60
  text "3" at 9779.25,7404.11 h60
  text "Top Layer" at 10189.17,7404.11 h60
  text "Copper" at 11118.91,7404.11 h60
  text "0,070mm" at 11978.68,7404.11 h60
  text "4" at 9779.25,7284.11 h60
  text "Dielectric 2" at 10189.17,7284.11 h60
  text "FR-4" at 11118.91,7284.11 h60
  text "0,380mm" at 11978.68,7284.11 h60
  text "4,2" at 12628.51,7284.11 h60
  text "5" at 9779.25,7164.11 h60
  text "GND" at 10189.17,7164.11 h60
  text "Copper" at 11118.91,7164.11 h60
  text "0,070mm" at 11978.68,7164.11 h60
  text "6" at 9779.25,7044.11 h60
  text "Dielectric1" at 10189.17,7044.11 h60
  text "FR-4" at 11118.91,7044.11 h60
  text "0,500mm" at 11978.68,7044.11 h60
  text "4,2" at 12628.51,7044.11 h60
  text "7" at 9779.25,6924.11 h60
  text "POWER" at 10189.17,6924.11 h60
  text "Copper" at 11118.91,6924.11 h60
  text "0,070mm" at 11978.68,6924.11 h60
  text "8" at 9779.25,6804.11 h60
  text "Dielectric 3" at 10189.17,6804.11 h60
  text "FR-4" at 11118.91,6804.11 h60
  text "0,380mm" at 11978.68,6804.11 h60
  text "4,2" at 12628.51,6804.11 h60
  text "9" at 9779.25,6684.11 h60
  text "Bottom Layer" at 10189.17,6684.11 h60
  text "Copper" at 11118.91,6684.11 h60
  text "0,070mm" at 11978.68,6684.11 h60
  text "10" at 9779.25,6564.11 h60
  text "Bottom Solder" at 10189.17,6564.11 h60
  text "Solder Resist" at 11118.91,6564.11 h60
  text "0,025mm" at 11978.68,6564.11 h60
  text "3,5" at 12628.51,6564.11 h60
  text "11" at 9779.25,6444.11 h60
  text "Bottom Overlay" at 10189.17,6444.11 h60
  text ".Layer_Name" at 536.41,-906.9 h60
M13 Component Bodies Top:
  text ".Layer_Name" at 536.41,-906.9 h60
M14 Component Bodies Bottom:
  text ".Layer_Name" at 536.41,-906.9 h60
M15 Courtyards Top:
  text ".Layer_Name" at 536.41,-906.9 h60
M16 Courtyards Bottom:
  text ".Layer_Name" at 536.41,-906.9 h60
Drill Drawing:
  circle w10: c5308.31,2855.88 r22.14
  lines w10: 5286.17,2745.19 5297.24,2745.19 5308.31,2734.12 5319.37,2745.19 5330.44,2745.19 5319.37,2756.26 5330.44,2767.33 5319.37,2767.33 5308.31,2778.4 5297.24,2767.33 5286.17,2767.33 5297.24,2756.26 5286.17,2745.19 ; 5286.17,2977.64 5330.44,2977.64 5308.31,2933.37 5286.17,2977.64 ; 5286.17,3032.99 5308.31,3044.06 5330.44,3032.99 5319.37,3055.13 5330.44,3077.27 5308.31,3066.2 5286.17,3077.27 5297.24,3055.13 5286.17,3032.99 ; 5286.17,3132.61 5330.44,3132.61 5330.44,3176.89 5286.17,3176.89 5286.17,3132.61 ; 5286.17,3243.3 5297.24,3243.3 5297.24,3232.23 5319.37,3232.23 5319.37,3243.3 5330.44,3243.3 5330.44,3265.44 5319.37,3265.44 5319.37,3276.51 5297.24,3276.51 5297.24,3265.44 5286.17,3265.44 5286.17,3243.3
  lines w12: 5245.41,2704.24 8358.35,2704.24 ; 5245.41,3301.97 8358.35,3301.97 ; 5561.04,2604.61 5561.04,3401.59 ; 5878.22,2604.61 5878.22,3401.59 ; 6499.97,2604.61 6499.97,3401.59 ; 6744.29,2604.61 6744.29,3401.59 ; 7104.63,2604.61 7104.63,3401.59 ; 7814.14,2604.61 7814.14,3401.59 ; 5245.41,2604.61 8358.35,2604.61 8358.35,3401.59 5245.41,3401.59 5245.41,2604.61
  text "Symbol" at 5305.18,3331.86 h72
  text "Quantity" at 5590.93,3331.86 h72
  text "Finished Hole Size" at 5908.11,3331.86 h72
  text "Plated" at 6529.85,3331.86 h72
  text "Hole Type" at 6774.18,3331.86 h72
  text "Drill Layer Pair" at 7134.52,3331.86 h72
  text "Hole Tolerance" at 7844.03,3331.86 h72
  text "17" at 5590.93,3232.23 h60
  text "7.87mil (0.200mm)" at 5908.11,3232.23 h60
  text "PTH" at 6529.85,3232.23 h60
  text "Round" at 6774.18,3232.23 h60
  text "Top Layer - Bottom Layer" at 7134.52,3232.23 h60
  text "525" at 5590.93,3132.61 h60
  text "8.00mil (0.203mm)" at 5908.11,3132.61 h60
  text "PTH" at 6529.85,3132.61 h60
  text "Round" at 6774.18,3132.61 h60
  text "Top Layer - Bottom Layer" at 7134.52,3132.61 h60
  text "2" at 5590.93,3032.99 h60
  text "33.47mil (0.850mm)" at 5908.11,3032.99 h60
  text "PTH" at 6529.85,3032.99 h60
  text "Round" at 6774.18,3032.99 h60
  text "Top Layer - Bottom Layer" at 7134.52,3032.99 h60
  text "6" at 5590.93,2933.37 h60
  text "39.37mil (1.000mm)" at 5908.11,2933.37 h60
  text "PTH" at 6529.85,2933.37 h60
  text "Round" at 6774.18,2933.37 h60
  text "Top Layer - Bottom Layer" at 7134.52,2933.37 h60
  text "1" at 5590.93,2833.75 h60
  text "40.00mil (1.016mm)" at 5908.11,2833.75 h60
  text "PTH" at 6529.85,2833.75 h60
  text "Round" at 6774.18,2833.75 h60
  text "Top Layer - Bottom Layer" at 7134.52,2833.75 h60
  text "5" at 5590.93,2734.12 h60
  text "59.06mil (1.500mm)" at 5908.11,2734.12 h60
  text "PTH" at 6529.85,2734.12 h60
  text "Round" at 6774.18,2734.12 h60
  text "Top Layer - Bottom Layer" at 7134.52,2734.12 h60
  text "556 Total" at 5590.93,2634.5 h60
  text ".Layer_Name" at 536.41,-906.9 h60
M17 Embedded Cavity:
  text ".Layer_Name" at 536.41,-906.9 h60
M18 Embedded Assembly:
  text ".Layer_Name" at 536.41,-906.9 h60
M19 Embedded Keepout:
  text ".Layer_Name" at 536.41,-906.9 h60

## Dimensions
0,0 to 0,2559.06 on M2 Board Dimensions
0,2559.06 to 2351.88,2559.06 on M2 Board Dimensions
0,-368.11 to 1000,-368.11 on M2 Board Dimensions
